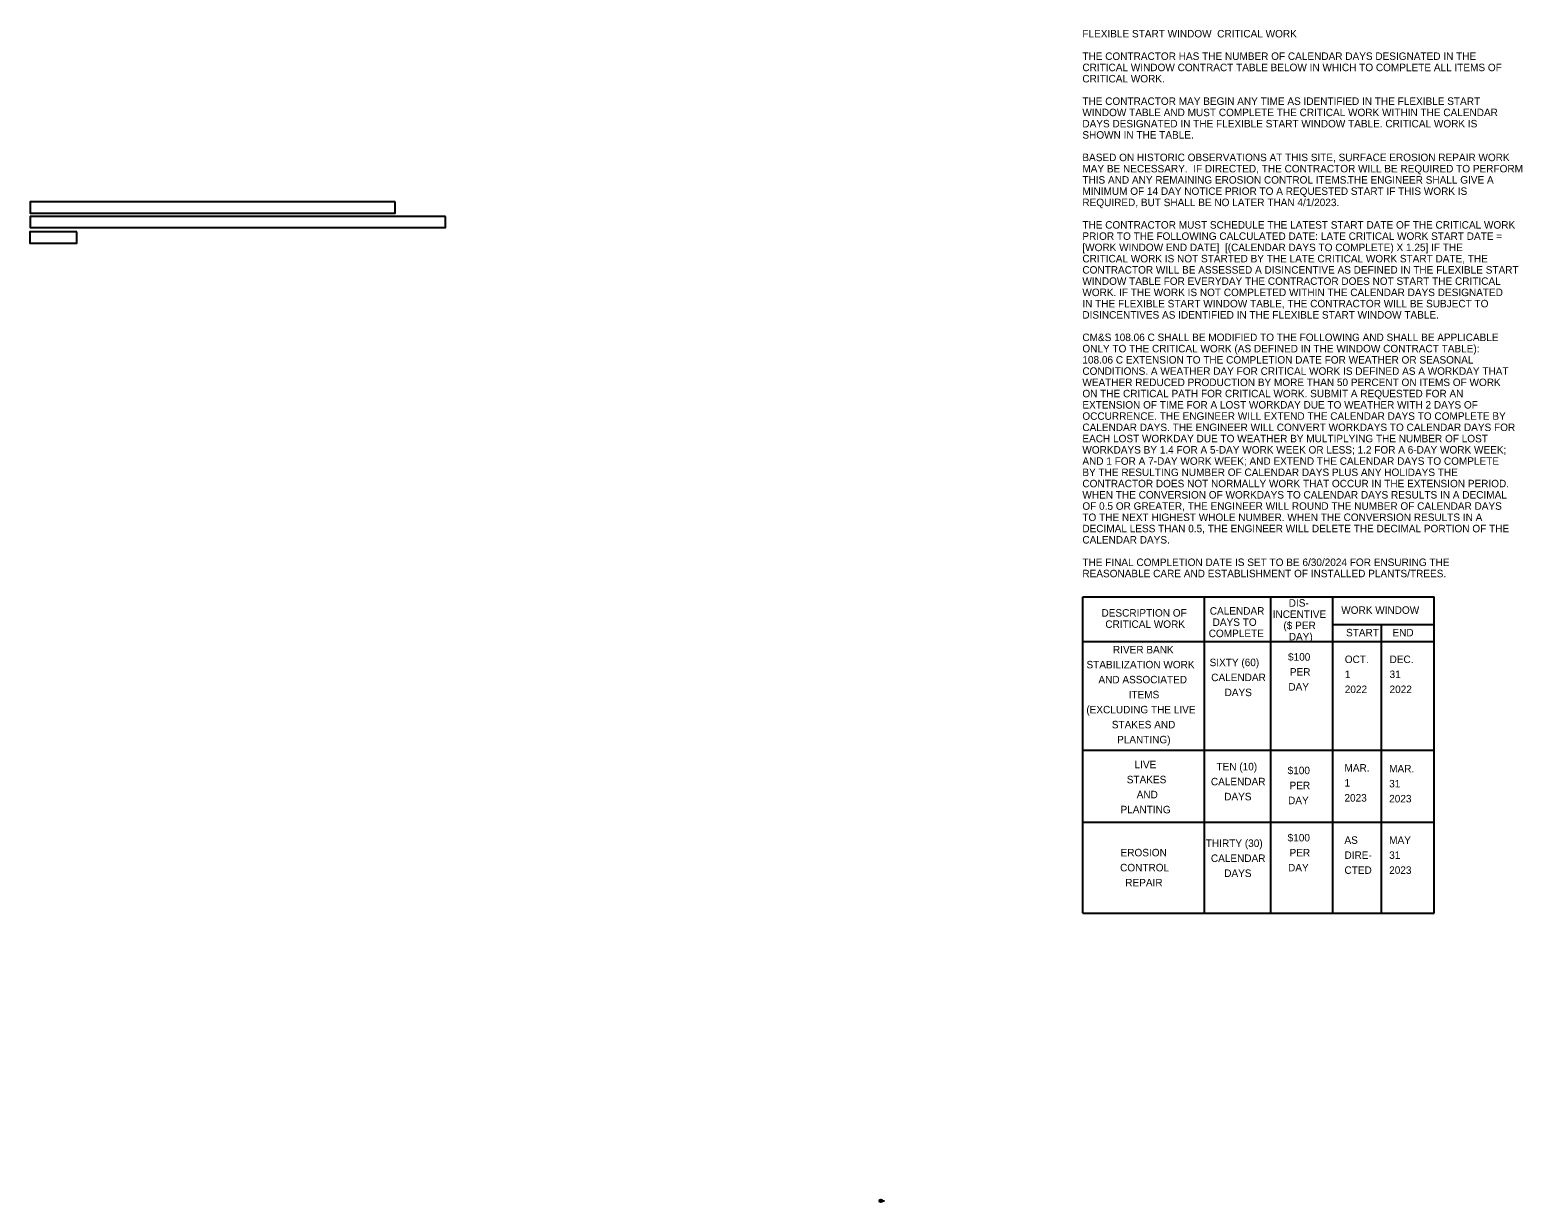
# Model space of a CAD drawing. Extents: x 0 to 63, y -1.2 to 22.
# Drawn here: x 35.11 to 62.98, y -1.18 to 20.71 of the extents above; entities that cross this region are included whole.
import ezdxf

# ---------------------------------------------------------------- set-up
doc = ezdxf.new("R2010")
doc.units = 0
for name, color, linetype in [('OC-GRID', 7, 'Continuous'), ('SH_Text', 7, 'Continuous'), ('TX_P_1', 7, 'Continuous')]:
    doc.layers.add(name, color=color, linetype=linetype)

msp = doc.modelspace()

# ---------------------------------------------------------------- linework, layer by layer
at = {"layer": 'OC-GRID'}
for points in [[(54.771, 10.126), (57.036, 10.126), (59.183, 10.126), (61.336, 10.126)], [(54.771, 4.217), (54.771, 10.126)], [(57.043, 4.217), (57.043, 9.605), (57.043, 10.105)], [(58.285, 4.231), (58.285, 9.605), (58.285, 10.105)], [(59.442, 4.231), (59.442, 10.103)], [(61.336, 4.217), (61.336, 7.135), (61.336, 10.126)], [(59.442, 9.605), (60.681, 9.605), (61.336, 9.605)], [(60.351, 4.22), (60.351, 9.605)], [(54.771, 9.291), (57.043, 9.291), (59.19, 9.291), (61.336, 9.291)], [(54.765, 7.263), (57.036, 7.263), (59.183, 7.263), (61.329, 7.263)], [(54.765, 5.915), (57.036, 5.915), (59.183, 5.915), (61.329, 5.915)], [(54.771, 4.217), (57.036, 4.217), (59.183, 4.217), (61.336, 4.217)]]:
    msp.add_lwpolyline(points, dxfattribs=at)
at = {"layer": 'SH_Text'}
for p, q in [((50.974, -1.152), (51.026, -1.152)), ((51, -1.152), (51.069, -1.152))]:
    msp.add_line(p, q, dxfattribs=at)
msp.add_circle((51, -1.152), 0.026, dxfattribs=at)
at = {"layer": 'TX_P_1'}
for points in [[(41.931, 17.501), (35.114, 17.501), (35.114, 17.29), (41.931, 17.29)], [(42.872, 17.229), (35.114, 17.229), (35.114, 17.018), (42.872, 17.018)], [(35.988, 16.939), (35.111, 16.939), (35.111, 16.728), (35.988, 16.728)]]:
    msp.add_lwpolyline(points, close=True, dxfattribs=at)

# ---------------------------------------------------------------- texts
at = {"layer": 'OC-GRID'}
for s, p in [('FLEXIBLE START WINDOW  CRITICAL WORK', (54.765, 20.57)), ('THE CONTRACTOR HAS THE NUMBER OF CALENDAR DAYS DESIGNATED IN THE ', (54.765, 20.15)), ('CRITICAL WINDOW CONTRACT TABLE BELOW IN WHICH TO COMPLETE ALL ITEMS OF ', (54.765, 19.94)), ('CRITICAL WORK. ', (54.765, 19.73)), ('WINDOW TABLE AND MUST COMPLETE THE CRITICAL WORK WITHIN THE CALENDAR ', (54.765, 19.1)), ('THE CONTRACTOR MAY BEGIN ANY TIME AS IDENTIFIED IN THE FLEXIBLE START ', (54.765, 19.31)), ('DAYS DESIGNATED IN THE FLEXIBLE START WINDOW TABLE. CRITICAL WORK IS ', (54.765, 18.89)), ('SHOWN IN THE TABLE. ', (54.765, 18.68)), ('BASED ON HISTORIC OBSERVATIONS AT THIS SITE, SURFACE EROSION REPAIR WORK ', (54.765, 18.26)), ('MAY BE NECESSARY.  IF DIRECTED, THE CONTRACTOR WILL BE REQUIRED TO PERFORM ', (54.765, 18.05)), ('THIS AND ANY REMAINING EROSION CONTROL ITEMS.  ', (54.765, 17.84)), ('THE ENGINEER SHALL GIVE A ', (59.72, 17.84)), ('MINIMUM OF 14 DAY NOTICE PRIOR TO A REQUESTED START IF THIS WORK IS ', (54.765, 17.63)), ('REQUIRED, BUT SHALL BE NO LATER THAN 4/1/2023.', (54.765, 17.42)), ('THE CONTRACTOR MUST SCHEDULE THE LATEST START DATE OF THE CRITICAL WORK ', (54.765, 17)), ('[WORK WINDOW END DATE]  [(CALENDAR DAYS TO COMPLETE) X 1.25] IF THE ', (54.765, 16.58)), ('PRIOR TO THE FOLLOWING CALCULATED DATE: LATE CRITICAL WORK START DATE = ', (54.765, 16.79)), ('CRITICAL WORK IS NOT STARTED BY THE LATE CRITICAL WORK START DATE, THE ', (54.765, 16.37)), ('CONTRACTOR WILL BE ASSESSED A DISINCENTIVE AS DEFINED IN THE FLEXIBLE START ', (54.765, 16.16)), ('WINDOW TABLE FOR EVERYDAY THE CONTRACTOR DOES NOT START THE CRITICAL ', (54.765, 15.95)), ('WORK. IF THE WORK IS NOT COMPLETED WITHIN THE CALENDAR DAYS DESIGNATED ', (54.765, 15.74)), ('IN THE FLEXIBLE START WINDOW TABLE, THE CONTRACTOR WILL BE SUBJECT TO ', (54.765, 15.53)), ('DISINCENTIVES AS IDENTIFIED IN THE FLEXIBLE START WINDOW TABLE.  ', (54.765, 15.32)), ('CM&S 108.06 C SHALL BE MODIFIED TO THE FOLLOWING AND SHALL BE APPLICABLE ', (54.765, 14.9)), ('ONLY TO THE CRITICAL WORK (AS DEFINED IN THE WINDOW CONTRACT TABLE): ', (54.765, 14.69)), ('108.06 C EXTENSION TO THE COMPLETION DATE FOR WEATHER OR SEASONAL ', (54.765, 14.48)), ('CONDITIONS. A WEATHER DAY FOR CRITICAL WORK IS DEFINED AS A WORKDAY THAT ', (54.765, 14.27)), ('WEATHER REDUCED PRODUCTION BY MORE THAN 50 PERCENT ON ITEMS OF WORK ', (54.765, 14.06)), ('ON THE CRITICAL PATH FOR CRITICAL WORK. SUBMIT A REQUESTED FOR AN ', (54.765, 13.85)), ('EXTENSION OF TIME FOR A LOST WORKDAY DUE TO WEATHER WITH 2 DAYS OF ', (54.765, 13.64)), ('OCCURRENCE. THE ENGINEER WILL EXTEND THE CALENDAR DAYS TO COMPLETE BY ', (54.765, 13.43)), ('CALENDAR DAYS. THE ENGINEER WILL CONVERT WORKDAYS TO CALENDAR DAYS FOR ', (54.765, 13.22)), ('EACH LOST WORKDAY DUE TO WEATHER BY MULTIPLYING THE NUMBER OF LOST ', (54.765, 13.01)), ('WORKDAYS BY 1.4 FOR A 5-DAY WORK WEEK OR LESS; 1.2 FOR A 6-DAY WORK WEEK; ', (54.765, 12.8)), ('AND 1 FOR A 7-DAY WORK WEEK; AND EXTEND THE CALENDAR DAYS TO COMPLETE ', (54.765, 12.59)), ('CONTRACTOR DOES NOT NORMALLY WORK THAT OCCUR IN THE EXTENSION PERIOD. ', (54.765, 12.17)), ('BY THE RESULTING NUMBER OF CALENDAR DAYS PLUS ANY HOLIDAYS THE ', (54.765, 12.38)), ('WHEN THE CONVERSION OF WORKDAYS TO CALENDAR DAYS RESULTS IN A DECIMAL ', (54.765, 11.96)), ('OF 0.5 OR GREATER, THE ENGINEER WILL ROUND THE NUMBER OF CALENDAR DAYS ', (54.765, 11.75)), ('TO THE NEXT HIGHEST WHOLE NUMBER. WHEN THE CONVERSION RESULTS IN A ', (54.765, 11.54)), ('DECIMAL LESS THAN 0.5, THE ENGINEER WILL DELETE THE DECIMAL PORTION OF THE ', (54.765, 11.33)), ('CALENDAR DAYS.', (54.765, 11.12)), ('THE FINAL COMPLETION DATE IS SET TO BE 6/30/2024 FOR ENSURING THE ', (54.765, 10.7)), ('REASONABLE CARE AND ESTABLISHMENT OF INSTALLED PLANTS/TREES.', (54.765, 10.49)), ('DIS-', (58.618, 9.941)), ('DESCRIPTION OF ', (55.122, 9.755)), ('CALENDAR', (57.144, 9.792)), ('INCENTIVE ', (58.319, 9.731)), ('WORK WINDOW', (59.599, 9.807)), ('CRITICAL WORK', (55.194, 9.545)), ('COMPLETE', (57.124, 9.372)), ('DAYS TO', (57.198, 9.582)), ('($ PER', (58.519, 9.521)), ('START', (59.688, 9.387)), ('END', (60.555, 9.387)), ('RIVER BANK ', (55.336, 9.069)), ('DAY)', (58.619, 9.311)), ('STABILIZATION WORK ', (54.842, 8.789)), ('SIXTY (60)', (57.141, 8.83)), ('$100 ', (58.605, 8.933)), ('OCT. ', (59.665, 8.888)), ('DEC. ', (60.501, 8.888)), ('AND ASSOCIATED ', (55.065, 8.509)), ('CALENDAR', (57.171, 8.55)), ('PER ', (58.64, 8.653)), ('1', (59.665, 8.608)), ('31', (60.501, 8.608)), ('ITEMS ', (55.629, 8.229)), (' DAYS', (57.369, 8.27)), ('DAY', (58.612, 8.373)), ('2022 ', (59.665, 8.328)), ('2022 ', (60.501, 8.328)), ('(EXCLUDING THE LIVE ', (54.839, 7.949)), ('STAKES AND ', (55.315, 7.669)), ('PLANTING) ', (55.413, 7.389)), ('LIVE', (55.74, 6.923)), ('TEN (10)', (57.269, 6.885)), ('MAR. ', (59.659, 6.861)), ('MAR. ', (60.494, 6.846)), (' STAKES', (55.542, 6.643)), ('CALENDAR', (57.165, 6.605)), ('$100 ', (58.598, 6.813)), ('1', (59.659, 6.581)), ('31', (60.494, 6.566)), ('AND ', (55.779, 6.363)), (' DAYS', (57.362, 6.325)), ('PER ', (58.634, 6.533)), ('2023 ', (59.659, 6.301)), ('2023 ', (60.494, 6.286)), ('PLANTING ', (55.477, 6.083)), ('DAY', (58.606, 6.253)), ('THIRTY (30)', (57.071, 5.454)), ('$100 ', (58.598, 5.557)), ('AS ', (59.659, 5.512)), ('MAY ', (60.494, 5.512)), ('EROSION', (55.478, 5.279)), ('CALENDAR', (57.165, 5.174)), ('PER ', (58.634, 5.277)), ('DIRE-', (59.659, 5.232)), ('31', (60.494, 5.232)), ('CONTROL', (55.469, 4.999)), (' DAYS', (57.362, 4.894)), ('DAY', (58.606, 4.997)), ('CTED', (59.659, 4.952)), ('2023 ', (60.494, 4.952)), ('REPAIR ', (55.566, 4.719))]:
    msp.add_text(s, height=0.14, dxfattribs=at).set_placement(p)
at = {"layer": 'SH_Text'}
for s, p in [('2', (50.999, -1.146)), ('Default Comment', (51.033, -1.146)), ('1:1', (51.033, -1.162))]:
    msp.add_text(s, height=0.00328, dxfattribs=at).set_placement(p)

doc.saveas('drawing.dxf')
